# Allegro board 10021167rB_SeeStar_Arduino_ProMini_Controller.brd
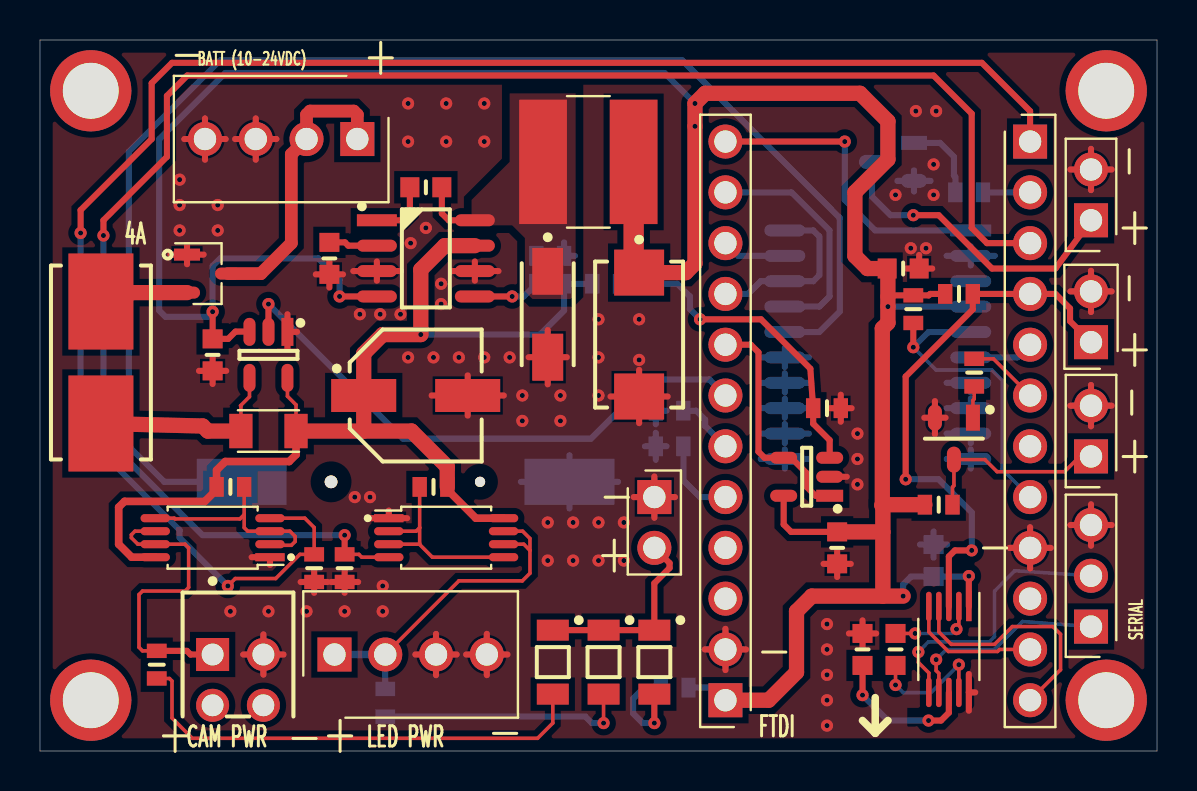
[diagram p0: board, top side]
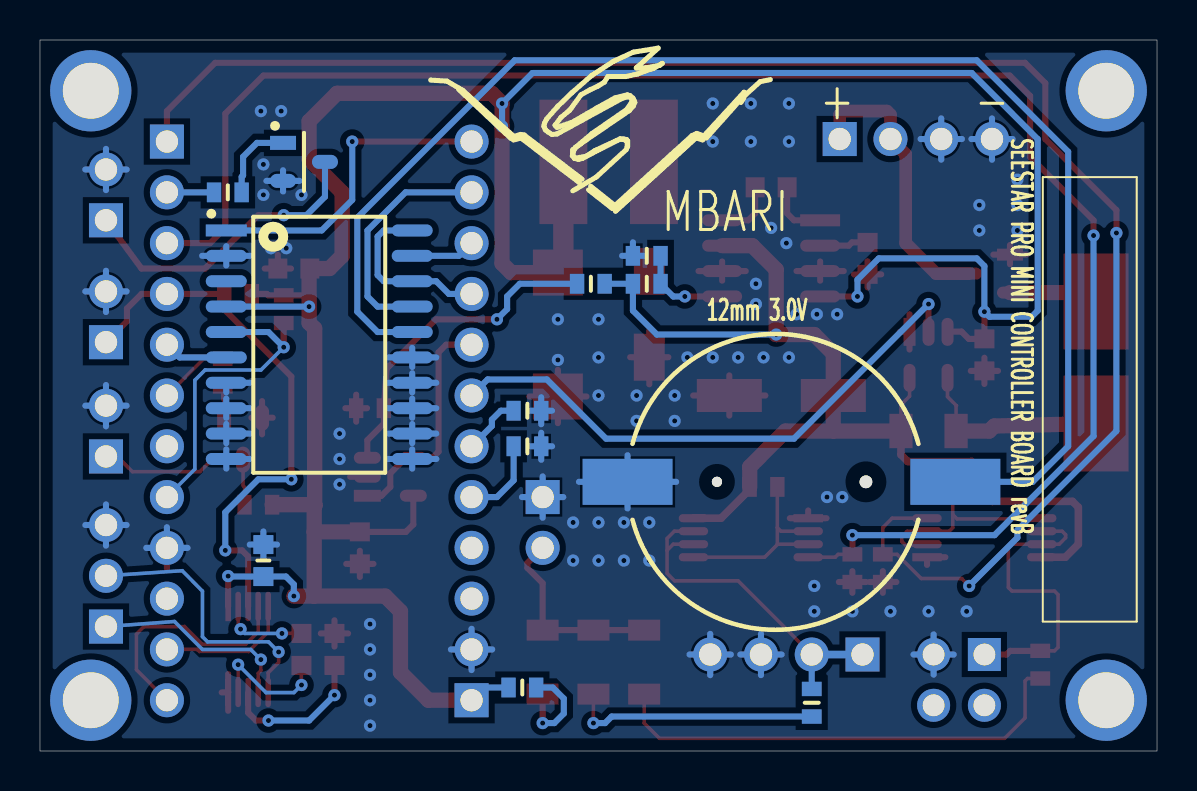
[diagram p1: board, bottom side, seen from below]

Outline 55.88 x 35.56 mm; copper layers: TOP, BOTTOM. Coordinates in mm from the lower left corner of the outline.
Outline path: 0,35.56 0,0 55.88,0 55.88,35.56 0,35.56

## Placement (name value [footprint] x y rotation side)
BT1  S8411-45R  [HARWIN_S8411-45R]  18.29 13.46 90 bottom
C1  0.1uF  [CAPC1608X90N]  19.3 28.19 0 top
C2  47uF  [CAPAE660X800N]  18.8 17.78 0 top
C3  68uF  [CAPMP7343X310N]  29.97 20.83 270 top
C4  0.10uF  [CAPC1608X87N]  8.64 19.81 270 top
C5  0.1uF  [CAPC1608X90N]  14.48 24.64 270 top
C6  0.10uF  [CAPC1608X87N]  44.7 9.53 90 bottom
C7  0.10uF  [CAPC1608X87N]  42.8 5.08 270 top
C8  0.10uF  [CAPC1608X87N]  41.15 5.08 90 top
C9  0.10uF  [CAPC1608X87N]  43.18 24.13 0 top
C10  0.10uF  [CAPC1608X87N]  39.88 10.16 270 top
D1  B340A-13-F  [DIOM5226X230N]  25.4 21.84 270 top
D2  LTST-C150TBKT  [LED_LTST-C150XXX]  25.65 4.45 270 top
D3  LTST-C150KRKT  [LED_LTST-C150XXX]  28.19 4.45 270 top
D4  LTST-C150KGKT  [LED_LTST-C150XXX]  30.73 4.45 270 top
F1  0154004.DRT  [FUSM9750X381N]  3.05 19.43 270 top
J1  1725672  [PHOENIX_1725672]  12.06 30.61 180 top
J2  SSW-102-01-T-S  [SAMTEC_SSW-102-XX-XXX-S-X]  52.58 27.81 90 top
J3  1725656  [PHOENIX_1725656]  8.64 4.83 0 top
J4  SSW-103-01-T-S  [SAMTEC_SSW-103-XX-XXX-S-X]  52.58 8.76 90 top
J5  1725672  [PHOENIX_1725672]  18.54 4.83 0 top
J6  SSW-112-01-T-S  [SAMTEC_SSW-112-XX-XXX-S-X]  34.29 16.51 90 top
J7  SSW-112-01-T-S  [SAMTEC_SSW-112-XX-XXX-S-X]  49.53 16.51 270 top
J8  TSW-102-17-T-S  [SAMTEC_TSW-102-17-X-S]  30.73 11.43 270 top
J9  SSW-102-01-T-S  [SAMTEC_SSW-102-XX-XXX-S-X]  52.58 16 90 top
J10  TSW-102-17-T-S  [SAMTEC_TSW-102-17-X-S]  52.58 21.72 90 top
L1  33uH  [IND_SRN6045]  27.43 29.46 0 top
NOREF  -  []  0 0 0 top
NOREF#2  -  []  55.88 0 90 top
NOREF#3  -  []  55.88 0 90 top
NOREF#4  -  []  50.8 33.02 180 top
NOREF#5  -  [unnamed#2]  2.54 2.54 0 top
NOREF#6  -  []  0 0 0 top
NOREF#7  -  [unnamed#2]  53.34 33.02 0 top
NOREF#8  -  []  249.81 111.38 0 top
NOREF#9  -  []  0 0 0 top
NOREF#10  -  []  -50.8 -76.2 0 top
NOREF#11  -  [unnamed#2]  2.54 33.02 0 top
NOREF#12  -  [unnamed#2]  53.34 2.54 0 top
NOREF#13  -  []  55.88 0 90 top
NOREF#14  -  []  27.11 36.17 180 bottom
Q1  SI2369DS-T1-GE3  [SOT95P237X112-3L20N_132]  8.38 23.88 270 top
Q2  SI6562CDQ-T1-GE3  [SOP65P640X120-8L30N]  8.64 10.67 90 top
Q3  SI6562CDQ-T1-GE3  [SOP65P640X120-8L30N]  20.32 10.67 270 top
Q4  MMBT3904  [SOT95P240X130-3N_123]  42.67 29.46 180 bottom
Q5  MMBT3904  [SOT95P240X130-3N_123]  45.72 15.62 270 top
R1  0.02  [RESC3015X65N]  11.43 16 0 top
R2  1.00M  [RESC1608X50N]  25.53 23.37 180 bottom
R3  121.0K  [RESC1608X50N]  28.32 23.37 0 bottom
R4  22.1K  [RESC1608X50N]  39.37 17.14 0 top
R5  383.0K  [RESC1608X50N]  25.53 24.77 0 bottom
R6  100.0K  [RESC1608X50N]  9.53 13.21 0 top
R7  100.0K  [RESC1608X50N]  45.97 22.86 0 top
R8  100.0K  [RESC1608X50N]  13.72 9.14 270 top
R9  100.0K  [RESC1608X50N]  19.68 13.21 180 top
R10  100.0K  [RESC1608X50N]  15.24 9.14 270 top
R11  1.69K  [RESC1608X50N]  5.84 4.32 270 top
R12  1.69K  [RESC1608X50N]  17.27 2.41 270 bottom
R13  294  [RESC1608X50N]  31.75 3.17 180 bottom
R14  100.0K  [RESC1608X50N]  43.69 22.1 270 top
R15  10.0K  [RESC1608X50N]  46.48 27.94 180 bottom
R16  0.0  [RESC1608X50N]  31.5 17.02 180 bottom
R17  0.0  [RESC1608X50N]  31.5 15.24 180 bottom
R18  10.0K  [RESC1608X50N]  46.74 18.92 270 top
R19  100.0K  [RESC1608X50N]  44.96 12.32 0 top
U1  MAX5035BASA+  [SOIC127P600X175-8N]  19.3 24.64 0 top
U2  MAX4372FEUK+T  [SOT95P280X145-5N]  11.43 19.81 270 top
U3  AD8603AUJZ  [SOT95P280X100-5N]  38.35 13.72 180 top
U4  MAX3311CUB+  [SOP50P490X110-10L30N]  45.47 5.08 180 top
U5  DS3234S#  [SOIC127P1032X265-20N]  41.91 20.32 180 bottom

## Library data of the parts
BT1 = BATTERY
C1 C4-C10 = CAP
C2 C3 = CAP_P
D1 = DIODE_SCHOTTKY
D2-D4 = LED
F1 = FUSEHOLDER_2T_2PIN
J1 J5 = CON4
J2 J3 J8-J10 = CON2
J4 = CON3
J6 J7 = CON12
L1 = IND
Q1 = MOSFET_I_EP_GSD
Q2 Q3 = MOSFET_I_PN_DSSGGSSD
Q4 Q5 = BJT_NPN_BCE
R1-R19 = RES
U1 = MAX5035
U2 = MAX4372xEUK-T_SYM-MOD1
U3 = AD8603
U4 = MAX3311
U5 = DS3234Sx

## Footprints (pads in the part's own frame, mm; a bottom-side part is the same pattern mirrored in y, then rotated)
CAPAE660X800N
  rect 3.251x1.651 smd: 1(-2.601,0) 2(2.601,0)
CAPC1608X87N
  rect 0.95x1.001 smd: 1(-0.8,0) 2(0.8,0)
CAPC1608X90N
  rect 0.95x1.001 smd: 1(-0.8,0) 2(0.8,0)
CAPMP7343X310N
  rect 2.301x2.499 smd: 1(-3.099,0) 2(3.099,0)
DIOM5226X230N
  rect 2.349x1.549 smd: A(2.149,0) C(-2.149,0)
FUSM9750X381N
  rect 4.801x3.251 smd: 1(-3.051,0) 2(3.051,0)
HARWIN_S8411-45R
  round 0.635 hole 1.27 unplated: (0,-3.726)
  round 0.508 hole 1.016 unplated: (0,3.726)
  rect 2.301x4.501 smd: 1(0,-8.199) 2(0,8.199)
IND_SRN6045
  rect 2.39x6.22 smd: 1(-2.266,0) 2(2.266,0)
LED_LTST-C150XXX
  rect 1.049x1.6 smd: A(1.6,0) C(-1.6,0)
PHOENIX_1725656
  round 1.651 hole 1.092: (0,-2.54) (2.54,-2.54) 2(2.54,0)
  rect 1.651x1.651 hole 1.092: 1(0,0)
PHOENIX_1725672
  rect 1.702x1.702 hole 1.118: 1(-3.81,0)
  round 1.702 hole 1.118: 2(-1.27,0) 3(1.27,0) 4(3.81,0)
RESC1608X50N
  rect 0.719x0.991 smd: 1(-0.691,0) 2(0.691,0)
RESC3015X65N
  rect 1.161x1.72 smd: 1(-1.379,0) 2(1.379,0)
SAMTEC_SSW-102-XX-XXX-S-X
  rect 1.702x1.702 hole 1.118: 1(-1.27,0)
  round 1.702 hole 1.118: 2(1.27,0)
SAMTEC_SSW-103-XX-XXX-S-X
  rect 1.702x1.702 hole 1.118: 1(-2.54,0)
  round 1.702 hole 1.118: 2(0,0) 3(2.54,0)
SAMTEC_SSW-112-XX-XXX-S-X
  rect 1.702x1.702 hole 1.118: 1(-13.97,0)
  round 1.702 hole 1.118: 2(-11.43,0) 3(-8.89,0) 4(-6.35,0) 5(-3.81,0) 6(-1.27,0) 7(1.27,0) 8(3.81,0) 9(6.35,0) 10(8.89,0) 11(11.43,0) 12(13.97,0)
SAMTEC_TSW-102-17-X-S
  rect 1.702x1.702 hole 1.118: 1(-1.27,0)
  round 1.702 hole 1.118: 2(1.27,0)
SOIC127P600X175-8N
  rect 1.999x0.599 smd: 1(-2.451,1.905)
  oval 1.999x0.599 smd: 2(-2.451,0.635) 3(-2.451,-0.635) 4(-2.451,-1.905) 5(2.451,-1.905) 6(2.451,-0.635) 7(2.451,0.635) 8(2.451,1.905)
SOIC127P1032X265-20N
  rect 2.05x0.599 smd: 1(-4.651,5.715)
  oval 2.05x0.599 smd: 2(-4.651,4.445) 3(-4.651,3.175) 4(-4.651,1.905) 5(-4.651,0.635) 6(-4.651,-0.635) 7(-4.651,-1.905) 8(-4.651,-3.175) 9(-4.651,-4.445) 10(-4.651,-5.715) 11(4.651,-5.715) 12(4.651,-4.445) 13(4.651,-3.175) 14(4.651,-1.905) 15(4.651,-0.635) 16(4.651,0.635) 17(4.651,1.905) 18(4.651,3.175) 19(4.651,4.445) 20(4.651,5.715)
SOP50P490X110-10L30N
  rect 0.279x1.471 smd: 1(-1.001,-2.149)
  oval 0.279x1.471 smd: 2(-0.5,-2.149) 3(0,-2.149) 4(0.5,-2.149) 5(1.001,-2.149) 6(1.001,2.149) 7(0.5,2.149) 8(0,2.149) 9(-0.5,2.149) 10(-1.001,2.149)
SOP65P640X120-8L30N
  rect 0.409x1.471 smd: 1(-0.975,-2.87)
  oval 0.409x1.471 smd: 2(-0.325,-2.87) 3(0.325,-2.87) 4(0.975,-2.87) 5(0.975,2.87) 6(0.325,2.87) 7(-0.325,2.87) 8(-0.975,2.87)
SOT95P237X112-3L20N_132
  rect 0.599x1.3 smd: 1(-0.95,-1.026)
  oval 0.599x1.3 smd: 2(0.95,-1.026) 3(0,1.026)
SOT95P240X130-3N_123
  rect 1.3x0.701 smd: 1(-1.049,0.95)
  oval 1.3x0.701 smd: 2(1.049,0) 3(-1.049,-0.95)
SOT95P280X100-5N
  rect 1.349x0.599 smd: 1(-1.151,0.95)
  oval 1.349x0.599 smd: 2(-1.151,0) 3(-1.151,-0.95) 4(1.151,-0.95) 5(1.151,0.95)
SOT95P280X145-5N
  rect 1.4x0.599 smd: 1(-1.151,0.95)
  oval 1.4x0.599 smd: 2(-1.151,0) 3(-1.151,-0.95) 4(1.151,-0.95) 5(1.151,0.95)
unnamed#2
  round 4.064 hole 2.794: (0,0)

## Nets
5V: C3.1 C4.1 C6.1 C9.1 C10.1 J6.1 L1.2 R7.1 R13.1 R14.1 R19.1 U1.4(FB) U2.3(VCC) U3.5(V+) U4.1(VCC) U5.4(VCC)
GND_SIGNAL: BT1.2(-) C2.2 C3.2 C4.2 C5.2 C6.2 C8.2 C9.2 C10.2 D1.A J1.3 J1.4 J2.2 J3.2 J4.3 J5.3 J5.4 J6.2 J7.9 J8.1 J9.2 J10.2 Q1.1(G) Q2.1(D1) Q3.1(D1) Q4.3(E) Q5.3(E) R4.2 R5.2 R8.2 R10.2 R16.2 R17.2 U1.3(SGND) U1.6(GND) U2.1(GND) U3.2(V-) U4.10(GND) U5.2(NC2) U5.7(NC7) U5.8(NC8) U5.9(NC9) U5.10(NC10) U5.11(NC11) U5.12(NC12) U5.13(NC13) U5.14(NC14) U5.15(GND)
BATT: C2.1 Q2.8(D2) Q3.8(D2) R1.2 R2.1 R3.1 R6.1 R9.1 U1.7(VIN) U2.5(RS-)
BATT_CURR: J6.7 U2.2(OUT)
BATT_VOLT: J6.8 U3.1(OUT) U3.4(IN-)
CAM_ON: J7.2 R15.1
CAM_POWER: J7.1 Q2.4(G1) R8.1
LED_ON: J7.6 R18.1
LED_POWER: J7.3 Q3.4(G1) R10.1
MISO: J6.10 U5.19(DOUT)
MOSI: J6.11 U5.17(DIN)
RTC_INT: J7.8 R14.2 U5.5(I\N\T\/SQW)
RTC_RESET: J7.5 U5.6(R\S\T\)
RTC_SS: J6.12 U5.1(C\S\)
RXD: J7.11 U4.5(ROUT)
SCK: J6.9 U5.18(SCLK_1) U5.20(SCLK_0)
TXD: J7.12 U4.4(TIN)
UART_SHDN: J7.4 J10.1 R7.2 U4.3(\S\H\D\N)
N15152344: F1.1 Q1.2(S)
N15152348: F1.2 R1.1 U2.4(RS+)
N15152404: D4.A R13.2
N15152538: R3.2 R4.1 U3.3(IN+)
N15152776: Q2.2(S1B) Q2.3(S1A) Q2.5(G2) R6.2
N15152918: J2.1 Q4.2(C)
N15153066: BT1.1(+) U5.16(VBAT)
N15153250: Q4.1(B) R15.2
N15153266: J4.1 U4.7(TOUT)
N15153274: J4.2 U4.6(RIN)
N15153368: D2.A R11.2
N15153372: D3.A R12.2
N15153464: J3.1 Q2.6(D2A) Q2.7(S2B) R11.1
N15153536: J5.1 J5.2 Q3.6(D2A) Q3.7(S2B) R12.1
N15153652: D2.C D3.C D4.C J8.2
N15154300: R2.2 R5.1 U1.5(ON/\O\F\F\)
N15154372: C1.2 D1.C L1.1 U1.8(LX)
N15154432: C5.1 U1.2(VD)
N15154444: C1.1 U1.1(BST)
N15154620: J1.1 J1.2 Q1.3(D)
N15154692: Q3.2(S1B) Q3.3(S1A) Q3.5(G2) R9.2
N15157729: J9.1 Q5.2(C) R19.2
N15157767: Q5.1(B) R18.2
N15166192: C8.1 U4.8(V-)
N15166199: C7.2 U4.9(C1+)
N15166207: C7.1 U4.2(C1-)
N15174862: J6.6 R16.1
N15175191: J6.5 R17.1

Pads without a net: J6 3 4; J7 7 10; U5 3

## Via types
v1: diameter 0.61, hole 0.254, TOP to BOTTOM, 93 vias

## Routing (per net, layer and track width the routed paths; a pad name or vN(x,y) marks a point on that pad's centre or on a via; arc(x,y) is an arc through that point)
5V: length 145.9
  TOP w0.305: U4.1 v1(46.47,8.75) ; U3.5 37.2,11.33 37.57,10.96 C10.1 ; v1(8.64,21.97) C4.1 9.42,20.61 9.78,20.98 10.47,20.98 U2.3 ; 30.05,23.93 C3.1 ; v1(14.99,22.73) U1.4 ; 42.42,22.73 42.47,22.79 R14.1 44.46,22.79 44.53,22.86 R7.1
  TOP w0.762: 42.14,12.32 42.13,12.31 42.13,12.26 42.16,12.23 42.16,10.96 ; 42.14,12.32 R19.1 ; 42.14,12.32 42.14,21.13 42.42,21.41 v1(42.42,22.23) 42.42,24.09 C9.1 41.4,24.13 40.77,24.76 40.77,27.94 42.42,29.59 42.42,31.5 41.02,32.89 33.27,32.89 v1(32.77,32.38) v1(32.77,31.24) 32.77,24.38 32.31,23.93 30.05,23.93 ; 42.16,10.96 42.16,7.75 ; 42.16,10.96 C10.1 ; 42.16,7.75 38.61,7.75 37.85,6.99 37.85,3.94 36.45,2.54 J6.1 ; 42.16,7.75 v1(43.18,7.75)
  TOP w1.016: C3.1 29.97,24.49 29.7,24.77 L1.2
  BOTTOM w0.305: v1(32.77,31.24) v1(32.77,32.38) 31.24,33.91 9.27,33.91 5.97,30.61 5.97,22.02 6.27,21.72 8.38,21.72 v1(8.64,21.97) 8.64,24.26 9.02,24.64 13.92,24.64 14.99,23.57 v1(14.99,22.73) ; R13.1 33.66,3.17 J6.1 ; v1(43.18,7.75) 43.18,8.33 43.57,8.72 C6.1 46.44,8.72 v1(46.47,8.75) ; v1(42.42,22.23) U5.4
GND_SIGNAL: length 202.2
  TOP w0.305: 43.32,24.13 C9.2 ; C9.2 43.98,24.81 ; C9.2 44.64,24.13 ; 25.4,18.34 D1.A ; D1.A 25.4,21.05 ; D1.A 24.44,19.7 ; D1.A 26.36,19.7 ; J6.2 35.32,5.08 ; J6.2 34.29,6.11 ; J6.2 34.29,4.05 ; J6.2 33.26,5.08 ; J8.1 31.77,12.7 ; J8.1 30.73,11.67 ; J8.1 30.73,13.73 ; J8.1 29.7,12.7 ; R4.2 40.06,17.82 ; R4.2 40.6,17.14 ; R4.2 40.06,16.47 ; R4.2 39.52,17.14 ; U1.6 22.94,24 ; U1.6 21.76,24.48 ; U1.6 20.57,24 ; U1.6 21.76,23.52 ; C2.2 23.2,17.78 ; C2.2 19.59,17.78 ; C2.2 21.4,16.77 ; C2.2 21.4,18.79 ; C4.2 8.64,19.67 ; C4.2 8.64,18.36 ; C4.2 7.96,19.01 ; C4.2 9.32,19.01 ; Q3.1 18.37,11.64 ; Q3.1 16.53,11.64 ; Q3.1 17.45,12.03 ; 52.58,16.24 J9.2 ; J9.2 53.61,17.27 ; J9.2 51.55,17.27 ; J9.2 52.58,18.3 ; 44.24,16.67 Q5.3 ; Q5.3 44.77,17.5 ; Q5.3 44.77,15.84 ; Q5.3 45.3,16.67 ; J1.3 10.79,31.64 ; J1.3 11.83,30.61 ; J1.3 10.79,29.58 ; J1.3 9.76,30.61 ; 14.56,8.45 R10.2 ; R10.2 15.24,8.99 ; R10.2 15.92,8.45 ; R10.2 15.24,7.91 ; U2.1 12.86,20.96 ; U2.1 12.38,21.84 ; U2.1 12.38,20.08 ; U4.10 46.79,2.93 ; U4.10 46.47,3.85 ; U4.10 46.47,2.01 ; 29.97,16.4 C3.2 ; C3.2 29.97,19.06 ; C3.2 28.54,17.73 ; C3.2 31.4,17.73 ; C10.2 39.88,10.02 ; C10.2 39.2,9.36 ; C10.2 39.88,8.7 ; C10.2 40.56,9.36 ; C5.2 15.16,23.84 ; C5.2 14.48,23.18 ; C5.2 14.48,24.49 ; C5.2 13.8,23.84 ; J7.9 50.56,10.16 ; J7.9 49.53,9.13 ; J7.9 49.53,11.19 ; J7.9 48.5,10.16 ; 41.15,5.22 C8.2 ; C8.2 41.83,5.88 ; C8.2 40.47,5.88 ; C8.2 41.15,6.54 ; U3.2 40.36,13.72 ; Q1.1 8.19,24.83 ; Q1.1 7.36,25.31 ; Q1.1 6.53,24.83 ; Q1.1 7.36,24.35 ; 19.81,3.79 J5.3 ; J5.3 20.84,4.83 ; J5.3 19.81,5.86 ; J5.3 18.78,4.83 ; 16.85,23.52 U1.3 ; U1.3 16.85,24.48 ; U1.3 15.67,24 ; U1.3 18.03,24 ; R8.2 14.39,8.45 ; R8.2 13.72,7.91 ; R8.2 13.04,8.45 ; R8.2 13.72,8.99 ; J2.2 53.61,29.08 ; J2.2 52.58,30.11 ; J2.2 52.58,28.05 ; J2.2 51.55,29.08 ; 21.32,4.83 J5.4 ; J5.4 23.38,4.83 ; J5.4 22.35,5.86 ; J5.4 22.35,3.79 ; J4.3 52.58,12.33 ; J4.3 52.58,10.27 ; J4.3 51.55,11.3 ; J4.3 53.61,11.3 ; 11.51,9.31 Q2.1 10.59,9.69 ; 10.17,4.83 J3.2 ; J3.2 11.18,3.82 ; J3.2 12.18,4.83 ; J3.2 11.18,5.83 ; J10.2 52.58,24.02 ; J10.2 53.61,22.99 ; J10.2 51.55,22.99 ; J10.2 52.58,21.96 ; 8.26,30.61 8.26,31.64 ; 8.26,30.61 9.29,30.61 ; 8.26,30.61 8.26,29.58 ; 8.26,30.61 7.22,30.61
  BOTTOM w0.305: 51.55,11.3 J4.3 ; J4.3 53.61,11.3 ; J4.3 52.58,12.33 ; J4.3 52.58,10.27 ; 11.18,3.82 J3.2 ; J3.2 12.18,4.83 ; J3.2 11.18,5.83 ; J3.2 10.17,4.83 ; J8.1 30.73,13.73 ; J8.1 30.73,11.67 ; J8.1 29.7,12.7 ; J8.1 31.77,12.7 ; U5.13 38.47,17.14 ; U5.13 37.26,17.63 ; U5.13 37.26,16.66 ; U5.13 36.05,17.14 ; 8.26,29.58 8.26,30.61 ; 8.26,30.61 7.22,30.61 ; 8.26,30.61 8.26,31.64 ; 8.26,30.61 9.29,30.61 ; J5.3 20.84,4.83 ; J5.3 19.81,3.79 ; J5.3 18.78,4.83 ; J5.3 19.81,5.86 ; R5.2 26.22,25.44 ; R5.2 25.68,24.77 ; R5.2 26.76,24.77 ; 45.35,17.14 U5.8 ; U5.8 46.56,16.66 ; U5.8 46.56,17.63 ; 51.55,17.27 J9.2 ; J9.2 52.58,16.24 ; J9.2 52.58,18.3 ; J9.2 53.61,17.27 ; 30.81,16.34 R16.2 ; R16.2 30.81,17.69 ; R16.2 31.35,17.02 ; R16.2 30.26,17.02 ; J5.4 23.38,4.83 ; J5.4 21.32,4.83 ; J5.4 22.35,3.79 ; J5.4 22.35,5.86 ; 37.26,19.2 U5.15 ; U5.15 36.05,19.68 ; U5.15 37.26,20.17 ; U5.15 38.47,19.68 ; R17.2 30.81,15.92 ; R17.2 31.35,15.24 ; R17.2 30.81,14.56 ; R17.2 30.26,15.24 ; Q4.3 43.72,29.04 ; Q4.3 42.89,28.51 ; Q4.3 43.72,27.98 ; Q4.3 44.55,28.51 ; U5.2 47.77,24.77 ; U5.2 46.56,25.25 ; U5.2 46.56,24.28 ; U5.2 45.35,24.77 ; 52.58,28.05 J2.2 ; J2.2 53.61,29.08 ; J2.2 52.58,30.11 ; J2.2 51.55,29.08 ; 36.05,14.61 U5.11 ; U5.11 37.26,15.09 ; U5.11 38.47,14.61 ; U5.11 37.26,14.12 ; 44.02,10.33 C6.2 ; C6.2 44.7,10.98 ; C6.2 44.7,9.67 ; C6.2 45.38,10.33 ; U5.10 46.56,15.09 ; U5.10 45.35,14.61 ; U5.10 46.56,14.12 ; J1.3 11.83,30.61 ; J1.3 9.76,30.61 ; J1.3 10.79,29.58 ; J1.3 10.79,31.64 ; 36.05,15.88 U5.12 ; U5.12 37.26,15.39 ; U5.12 37.26,16.36 ; U5.12 38.47,15.88 ; J10.2 52.58,24.02 ; J10.2 51.55,22.99 ; J10.2 52.58,21.96 ; J10.2 53.61,22.99 ; 45.35,18.41 U5.7 46.56,17.93 ; 33.26,5.08 J6.2 ; J6.2 34.29,6.11 ; J6.2 35.32,5.08 ; J6.2 34.29,4.05 ; U5.9 46.56,16.36 ; U5.9 46.56,15.39 ; U5.9 45.35,15.88 ; 26.49,12.13 BT1.2 ; BT1.2 28.92,13.46 ; BT1.2 24.06,13.46 ; BT1.2 26.49,14.79 ; 48.5,10.16 J7.9 ; J7.9 50.56,10.16 ; J7.9 49.53,11.19 ; U5.14 37.26,18.9 ; U5.14 36.05,18.41 ; U5.14 38.47,18.41 ; U5.14 37.26,17.93
  vias: v1(6.99,28.57) v1(6.99,27.3) v1(6.99,26.04) v1(8.89,27.3) v1(8.89,26.04) v1(9.53,6.99) v1(11.43,6.99) v1(13.34,6.99) v1(15.24,6.99) v1(15.75,12.7) v1(16,21.84) v1(16.51,12.7) v1(17.02,21.84) v1(17.14,8.26) v1(17.14,6.99) v1(18.03,21.84) v1(18.41,32.38) v1(18.41,30.48) v1(18.41,19.68) v1(18.54,25.4) v1(19.3,26.16) v1(19.68,19.68) v1(20.07,23.37) v1(20.07,22.35) v1(20.32,32.38) v1(20.32,30.48) v1(20.95,19.68) v1(22.23,32.38) v1(22.23,30.48) v1(22.23,19.68) v1(23.5,19.68) v1(24.13,17.78) v1(24.13,16.51) v1(25.4,11.43) v1(25.4,9.53) v1(26.04,17.78) v1(26.04,16.51) v1(26.67,11.43) v1(26.67,9.53) v1(27.94,21.59) v1(27.94,19.68) v1(27.94,17.78) v1(27.94,11.43) v1(27.94,9.53) v1(29.21,11.43) v1(29.21,9.53) v1(29.97,21.59) v1(29.97,19.56) v1(39.37,6.35) v1(39.37,5.08) v1(39.37,3.81) v1(39.37,2.54) v1(39.37,1.27) v1(40.89,15.88) v1(40.89,14.61) v1(40.89,13.34) v1(42.8,27.81) v1(43.56,25.15) v1(43.81,32) v1(44.32,25.15) v1(44.7,29.34) v1(44.7,27.81) v1(44.83,32)
BATT: length 55.3
  TOP w0.178: R1.2 12.81,17.31 12.38,17.74 U2.5
  TOP w0.381: R1.2 12.81,14.82 12.47,14.48 9.27,14.48 8.83,14.04 R6.1 8.83,13.07 8.24,12.48 4.23,12.48 3.94,12.19 3.94,10.34 4.59,9.69 Q2.8 ; Q3.8 21.81,11.64 20.38,13.07 R9.1
  TOP w0.762: 16.2,16 C2.1 16.2,19.88 17.14,20.83 v1(19.05,20.83) 19.05,24.08 20.25,25.27 21.76,25.27 ; 16.2,16 R1.2 ; 16.2,16 18.59,16 20.38,14.21 R9.1
  BOTTOM w0.305: v1(19.05,20.83) 25.02,20.83 26.22,22.03 R2.1 R3.1
BATT_CURR: length 28.6
  TOP w0.305: U2.2 v1(11.43,22.35)
  BOTTOM w0.305: J6.7 33.49,18.58 30.52,18.58 27.56,15.62 18.16,15.62 v1(11.43,22.35)
BATT_VOLT: length 11.7
  TOP w0.305: J6.8 35.56,20.32 35.94,19.94 35.94,14.97 36.25,14.67 U3.4 37.58,14.67 38.35,13.89 38.35,13.21 38.8,12.77 U3.1
CAM_ON: length 2.4
  BOTTOM w0.305: R15.1 J7.2
CAM_POWER: length 85.3
  TOP w0.178: v1(9.4,8.26) 9.77,8.63 11.79,8.63 13,9.83 R8.1 13.72,11.18 13.25,11.64 Q2.4
  TOP w0.305: J7.1 49.53,32 47.12,34.42 6.6,34.42 5.59,33.4 5.59,30.61 2.03,27.05 v1(2.03,25.91)
  BOTTOM w0.305: v1(9.4,8.26) 6.99,10.67 6.99,11.05 2.03,16 v1(2.03,25.91)
LED_ON: length 3.6
  TOP w0.178: J7.6 47.7,19.61 R18.1
LED_POWER: length 86.1
  TOP w0.178: R10.1 15.95,9.83 16.1,9.69 Q3.4
  TOP w0.305: v1(3.17,25.78) 3.17,26.54 6.35,29.72 6.35,32.77 7.37,33.78 44.7,33.78 46.61,31.88 46.61,26.16 47.37,25.4 J7.3 ; v1(15.24,10.79) R10.1
  BOTTOM w0.305: v1(15.24,10.79) 8.13,10.79 3.17,15.75 v1(3.17,25.78)
MISO: length 3.2
  BOTTOM w0.305: U5.19 34.92,24.77 J6.10
MOSI: length 11.7
  BOTTOM w0.305: U5.17 38.99,22.23 39.5,22.73 39.5,26.04 37.59,27.94 J6.11
RTC_INT: length 16
  TOP w0.305: R14.2 v1(43.69,20.19)
  BOTTOM w0.178: v1(43.69,20.19) 44.83,19.06 47.62,19.06 48.13,18.54 48.13,14.1 J7.8
  BOTTOM w0.305: v1(43.69,20.19) 44.45,20.95 U5.5
RTC_RESET: length 3.2
  BOTTOM w0.305: J7.5 48.9,19.68 U5.6
RTC_SS: length 15.8
  TOP w0.305: v1(40.26,30.48) J6.12
  BOTTOM w0.305: U5.1 41.79,26.04 40.26,27.56 v1(40.26,30.48)
RXD: length 6.8
  TOP w0.178: J7.11 48,5.08 47.9,4.98 45.44,4.98 44.47,5.95 U4.5
SCK: length 8.9
  BOTTOM w0.305: J6.9 35.42,22.86 36.06,23.5 U5.18 38.68,23.5 38.99,23.8 38.99,25.73 38.68,26.04 U5.20
TXD: length 12.1
  TOP w0.178: J7.12 51.05,4.06 51.05,5.84 50.67,6.22 48.64,6.22 47.75,5.33 45.59,5.33 44.97,5.96 U4.4
UART_SHDN: length 27.6
  TOP w0.305: v1(46.61,10.03) 45.77,10.03 45.47,9.73 U4.3 ; J10.1 51.53,21.5 51.53,22.13 50.8,22.86 J7.4 R7.2 46.66,22.09 43.31,18.73 v1(43.31,13.59)
  BOTTOM w0.305: v1(43.31,13.59) 44.96,13.59 46.61,11.94 v1(46.61,10.03)
N15152344: length 4.4
  TOP w0.762: F1.1 4.64,22.93 Q1.2
N15152348: length 10
  TOP w0.178: R1.1 10.05,17.25 10.03,17.27 10.48,17.72 U2.4
  TOP w0.762: R1.1 8.39,16 8.14,16.25 F1.2
N15152404: length 5.1
  TOP w0.305: D4.A v1(30.73,1.4)
  BOTTOM w0.305: v1(30.73,1.4) 30.15,1.4 29.67,1.87 29.67,2.62 30.23,3.17 R13.2
N15152538: length 16.5
  TOP w0.305: v1(33.02,21.59) 36.07,21.59 38.54,19.12 R4.1 38.68,16.37 39.5,15.54 U3.3
  BOTTOM w0.305: R3.2 31.88,23.37 32.51,22.73 32.51,22.1 v1(33.02,21.59)
N15152776: length 10.9
  TOP w0.178: 10.22,11.82 10,11.61 6.76,11.61 6.72,11.64 Q2.5 ; 10.22,11.82 R6.2 ; 10.22,11.82 10.22,11.17 10.39,10.99 Q2.3 12.5,10.99 12.77,10.73 12.77,10.48 12.57,10.29 11.56,10.29 Q2.2
N15152918: length 15.4
  TOP w0.305: v1(43.69,26.8) 44.96,26.8 47.62,24.13 50.8,24.13 J2.1
  BOTTOM w0.305: v1(43.69,26.8) 42.55,26.8 41.62,27.72 Q4.2
N15153066: length 69.7
  BOTTOM w0.305: BT1.1 6.22,13.46 4.45,15.24 4.45,29.97 9.02,34.54 32.13,34.54 40.01,26.67 40.01,21.97 38.99,20.95 U5.16
N15153250: length 4.1
  BOTTOM w0.305: R15.2 45.79,28.71 45.72,28.79 45.72,29.72 45.02,30.41 Q4.1
N15153266: length 10.2
  TOP w0.178: v1(44.83,4.57) 44.83,4.02 44.97,3.89 U4.7
  BOTTOM w0.178: J4.1 49.15,6.48 47.75,5.08 45.34,5.08 v1(44.83,4.57)
N15153274: length 13.9
  TOP w0.178: v1(43.94,4.95) 43.94,4.43 44.47,3.91 U4.6
  BOTTOM w0.178: v1(43.94,4.95) 44.45,5.46 47.5,5.46 47.75,5.71 47.75,7.99 48.76,9.02 J4.2
N15153368: length 23.9
  TOP w0.178: R11.2 6.48,3.63 6.6,3.5 6.6,1.65 7.62,0.64 24.89,0.64 25.65,1.4 D2.A
N15153372: length 12.5
  TOP w0.178: v1(28.19,1.4) D3.A
  BOTTOM w0.305: v1(28.19,1.4) 27.61,1.4 27.28,1.72 R12.2
N15153464: length 15.6
  TOP w0.178: R11.1 5.13,5.01 4.95,5.18 4.95,7.82 5.13,8 7.26,8 7.44,8.18 7.44,10.17 7.26,10.34 Q2.7 4.89,10.34 4.57,10.67 4.57,10.82 4.75,10.99 Q2.6
  TOP w0.305: J3.1 7.53,4.83 7.35,5.01 R11.1
N15153536: length 17.8
  TOP w0.178: J5.2 20.95,8.51 24.13,8.51 24.51,8.89 24.51,10.03 ; 24.51,10.03 24.51,10.63 24.15,10.99 Q3.7 ; 24.51,10.03 24.2,10.34 Q3.6
  BOTTOM w0.305: J5.2 R12.1
  BOTTOM w0.381: J5.1 J5.2
N15153652: length 9.8
  TOP w0.305: J8.2 31.5,9.4 31.5,9.15 30.73,8.39 D4.C D3.C D2.C
N15154300: length 4.7
  TOP w0.305: U1.5 v1(23.62,22.73)
  BOTTOM w0.305: v1(23.62,22.73) 24.2,22.73 R2.2 R5.1
N15154372: length 3.1
  TOP w0.305: U1.8 20.45,26.54 20.1,26.89 C1.2
N15154432: length 2.4
  TOP w0.305: C5.1 15.26,25.44 15.42,25.27 16.85,25.27
N15154444: length 3.1
  TOP w0.305: C1.1 18.5,26.89 18.16,26.54 U1.1
N15154620: length 14.4
  TOP w0.635: J1.1 15.88,31.83 15.7,32 13.51,32 13.34,31.83 13.34,30.61 12.57,29.84 12.57,25.4 11.05,23.88 Q1.3
N15154692: length 10.5
  TOP w0.178: Q3.3 18.98,10.34 ; 18.98,10.34 19.63,9.69 Q3.5 ; 18.98,10.34 18.99,10.36 18.99,11.17 ; Q3.2 18.82,10.99 18.99,11.17 ; 18.99,11.17 R9.2
N15157729: length 9.8
  TOP w0.178: J9.1 52.14,14.86 51.25,13.97 47.88,13.97 47.28,14.57 Q5.2 45.72,13.27 45.65,13.2 R19.2
N15157767: length 1.6
  TOP w0.178: R18.2 46.74,17.6 46.67,17.54 Q5.1
N15166192: length 7.5
  TOP w0.305: v1(44.45,1.52) 45.07,1.52 45.47,1.92 U4.8 ; v1(41.15,2.79) C8.1
  BOTTOM w0.305: v1(44.45,1.52) 42.42,1.52 v1(41.15,2.79)
N15166199: length 6.3
  TOP w0.178: v1(42.8,3.3) C7.2 ; U4.9 v1(45.97,4.32)
  BOTTOM w0.178: v1(42.8,3.3) 43.18,2.92 44.57,2.92 v1(45.97,4.32)
N15166207: length 4.3
  TOP w0.178: v1(45.85,6.1) 45.97,6.22 U4.2 ; C7.1 v1(43.78,5.88)
  BOTTOM w0.178: v1(43.78,5.88) 45.63,5.88 v1(45.85,6.1)
N15174862: length 3
  BOTTOM w0.305: R16.1 32.83,17.02 33.27,16.57 33.27,16.26 J6.6
N15175191: length 4.2
  BOTTOM w0.305: J6.5 33.02,12.7 32.19,13.53 R17.1

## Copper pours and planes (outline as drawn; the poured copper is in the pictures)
GND_SIGNAL on TOP: 0.64,0.64 0.64,34.92 55.24,34.92 55.24,0.64 ; 8 cut-outs
GND_SIGNAL on BOTTOM: 0.64,34.92 55.24,34.92 55.24,0.64 0.64,0.64 ; 6 cut-outs
N15154372 on TOP: 21.59,26.29 21.59,27.56 23.5,29.46 23.5,32.89 26.8,32.89 26.8,22.86 26.54,22.61 24.64,22.61 24.26,22.99 24.26,25.65 23.62,26.29

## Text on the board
Ref Des/Silkscreen Bottom: 12mm 3.0V | SEESTAR PRO MINI CONTROLLER BOARD revB | - | +
Ref Des/Silkscreen Top: BATT (10-24VDC) | SERIAL | 4A | CAM PWR | LED PWR | FTDI | + | -
DISPLAY_TOP: FIGURE | SIZE | 10.0 | 43.0 | 44.0 | 110.0 | 40.0 | 50.0 | DRILL CHART: TOP to BOTTOM | ALL UNITS ARE IN MILS | PLATED | NON-PLATED | QTY | 93 | 4 | 43 | 1
